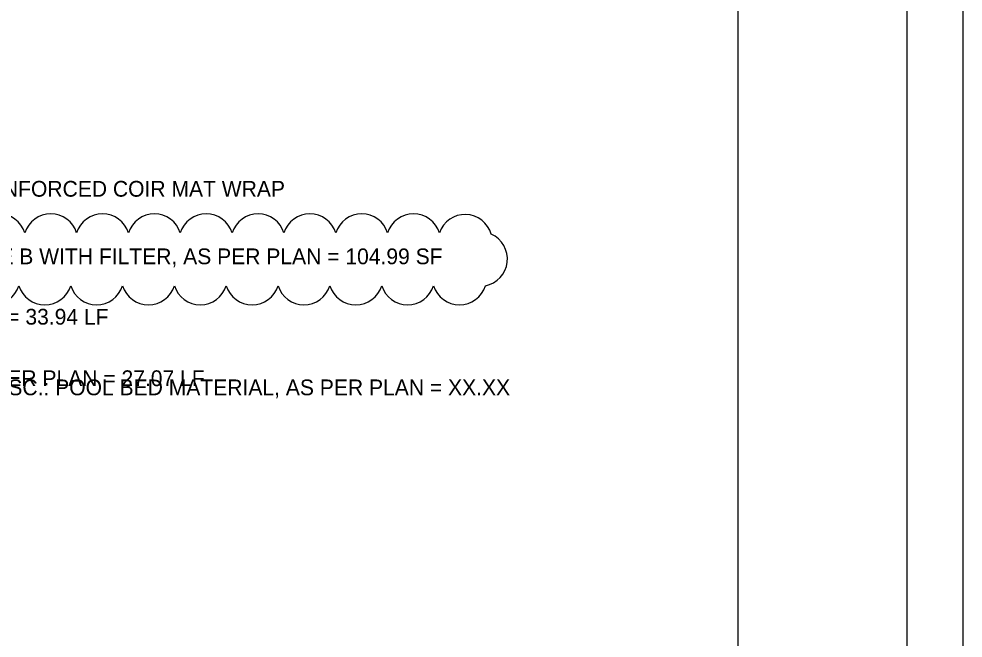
# Model space of a CAD drawing. Extents: x -34.1 to 34, y 0 to 22.
# Drawn here: x 25.61 to 34, y 5.5 to 11 of the extents above; entities that cross this region are included whole.
import ezdxf

# ---------------------------------------------------------------- set-up
doc = ezdxf.new("R2010")
doc.units = 0
for name, color, linetype in [('CS-ANNO', 7, 'Continuous'), ('CS-ANNO-MATC', 7, 'Continuous'), ('CS-ANNO-MATC-TEXT', 7, 'Continuous'), ('CS-ANNO-TABL', 7, 'Continuous')]:
    doc.layers.add(name, color=color, linetype=linetype)

msp = doc.modelspace()

# ---------------------------------------------------------------- linework, layer by layer
at = {"layer": 'CS-ANNO'}
msp.add_lwpolyline([(0, 0), (34, 0), (34, 22), (0, 22)], close=True, dxfattribs=at)
at = {"layer": 'CS-ANNO-MATC'}
msp.add_line((32, 0.5), (32, 21.5), dxfattribs=at)
msp.add_lwpolyline([(1.5, 21.5), (33.5, 21.5), (33.5, 0.5), (1.5, 0.5)], close=True, dxfattribs=at)
at = {"layer": 'CS-ANNO-MATC-TEXT'}
for centre, radius, start, end in [((25.4332, 9.0279), 0.2414, 17.5, 162.5), ((25.8937, 9.0279), 0.2414, 17.5, 162.5), ((26.3542, 9.0279), 0.2414, 17.5, 162.5), ((26.8147, 9.0279), 0.2414, 17.5, 162.5), ((27.2752, 9.0279), 0.2414, 17.5, 162.5), ((27.7358, 9.0279), 0.2414, 17.5, 162.5), ((28.1963, 9.0279), 0.2414, 17.5, 162.5), ((28.6568, 9.0279), 0.2414, 17.5, 162.5), ((29.1173, 9.0279), 0.2414, 17.5, 162.5), ((29.5757, 9.0215), 0.2414, 15.89128, 160.89128), ((29.7095, 8.8673), 0.2413, 280.94685, 65.94685), ((25.3804, 8.7022), 0.2414, 197.5, 342.5), ((25.8409, 8.7022), 0.2414, 197.5, 342.5), ((26.3014, 8.7022), 0.2414, 197.5, 342.5), ((26.762, 8.7022), 0.2414, 197.5, 342.5), ((27.2225, 8.7022), 0.2414, 197.5, 342.5), ((27.683, 8.7022), 0.2414, 197.5, 342.5), ((28.1435, 8.7022), 0.2414, 197.5, 342.5), ((28.604, 8.7022), 0.2414, 197.5, 342.5), ((29.0645, 8.7022), 0.2414, 197.5, 342.5), ((29.525, 8.7026), 0.2415, 197.59703, 342.59703)]:
    msp.add_arc(centre, radius, start, end, dxfattribs=at)

# ---------------------------------------------------------------- texts
for s, p in [('ITEM 203 ROADWAY, MISC.: VEGETATION REINFORCED COIR MAT WRAP', (21.3387, 9.4208)), ('ITEM 601 ROCK CHANNEL PROTECTION, TYPE B WITH FILTER, AS PER PLAN = 104.99 SF', (21.3387, 8.8208)), ('ITEM 659 SEEDING AND MULCHING CLASS 5B = 33.94 LF', (21.3041, 8.2845)), ('ITEM 670 SLOPE EROSION PROTECTION, AS PER PLAN = 27.07 LF', (21.2944, 7.7383))]:
    msp.add_text(s, height=0.14, dxfattribs=at).set_placement(p)
at = {"layer": 'CS-ANNO-TABL'}
msp.add_text("1' MINIMUM ROCK CHANNEL PROTECTION, MISC.: POOL BED MATERIAL, AS PER PLAN = XX.XX", height=0.14, dxfattribs=at).set_placement((21.3519, 7.6571))

doc.saveas('drawing.dxf')
